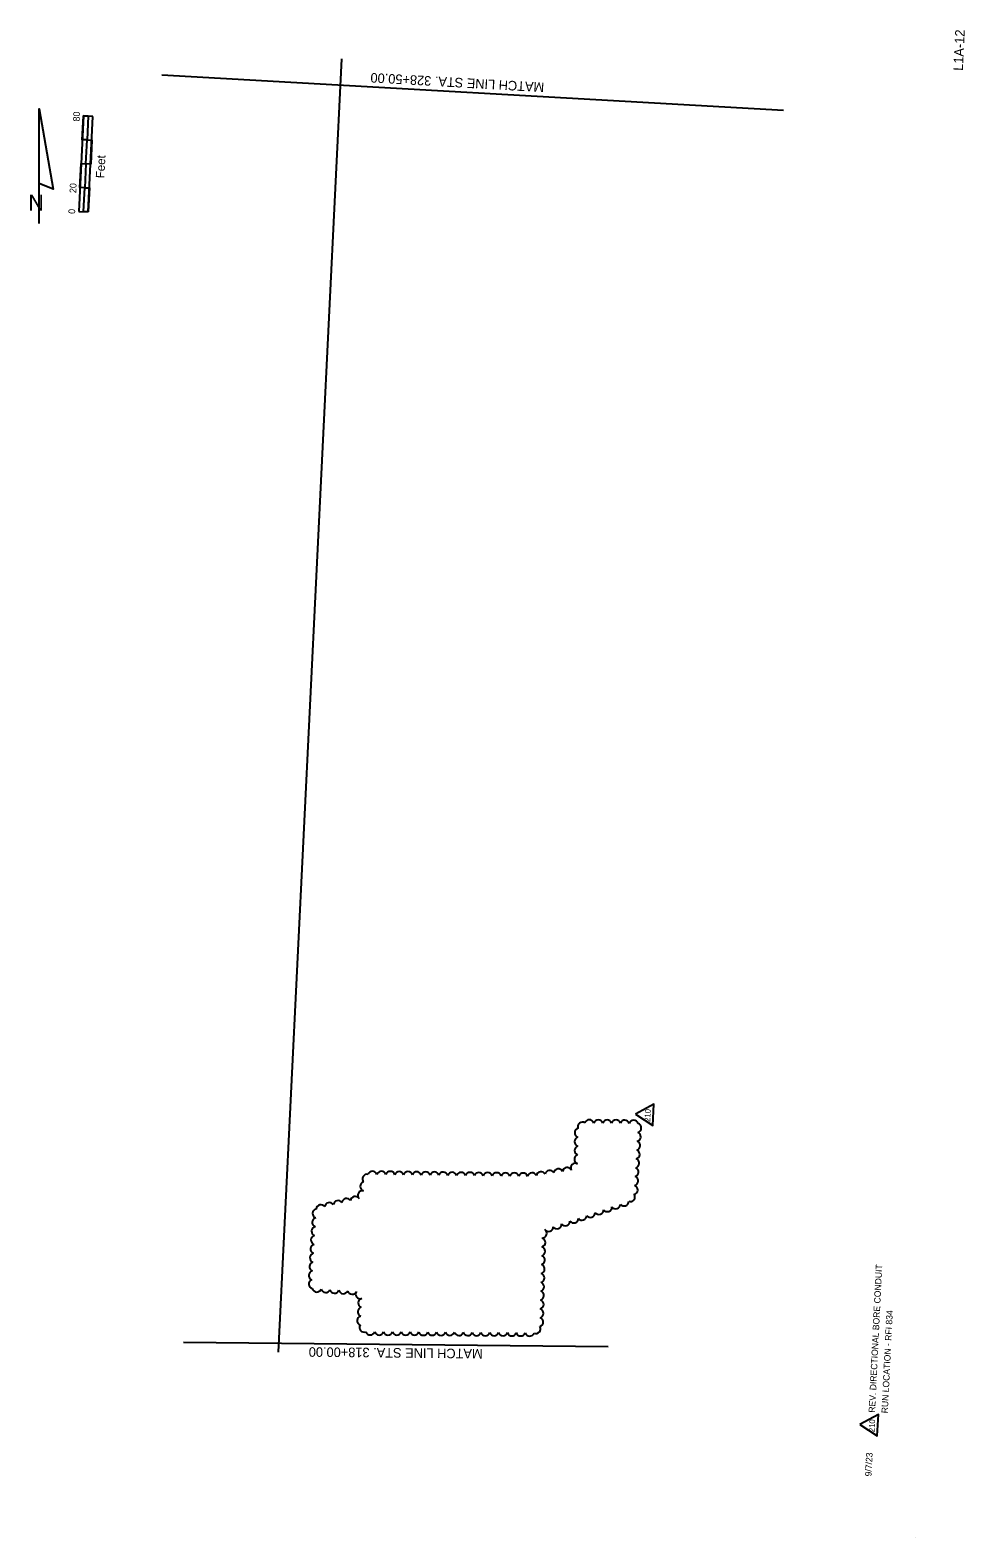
# Model space of a CAD drawing. Extents: x 929471 to 930252, y 607965 to 609226.
import ezdxf

# ---------------------------------------------------------------- set-up
doc = ezdxf.new("R2010")
doc.units = 0
for name, color, linetype in [('ActivePointCell_dp', 7, 'Continuous'), ('AdhocPoint_dp', 7, 'Continuous'), ('Cloud_dp', 7, 'Continuous'), ('NonPlottingEle_dp', 7, 'Continuous'), ('TextMinor', 7, 'Continuous'), ('TextMisc', 7, 'Continuous'), ('TextShtNo', 7, 'Continuous')]:
    doc.layers.add(name, color=color, linetype=linetype)

msp = doc.modelspace()

# ---------------------------------------------------------------- linework, layer by layer
at = {"layer": 'ActivePointCell_dp'}
msp.add_line((929678.7, 608120.4), (929731.6, 609202.3), dxfattribs=at)
at = {"layer": 'AdhocPoint_dp'}
msp.add_line((930211.2, 607965), (930211.2, 607965), dxfattribs=at)
at = {"layer": 'Cloud_dp'}
for points in [[(929977.1, 608319.4), (929991.7, 608310), (929992.6, 608327.7)], [(930164.7, 608059.8), (930179.3, 608050.4), (930180.2, 608068.1)]]:
    msp.add_lwpolyline(points, close=True, dxfattribs=at)
for centre, start, end in [((929932.7, 608308.9), 55.7899, 200.7899), ((929938.6, 608310.9), 16.7545, 161.7545), ((929946, 608310.8), 16.7545, 161.7545), ((929953.4, 608310.7), 16.7545, 161.7545), ((929960.8, 608310.7), 16.7545, 161.7545), ((929968.2, 608310.6), 16.7545, 161.7545), ((929975.6, 608310.5), 16.7545, 161.7545), ((929930.1, 608296.4), 106.7545, 251.7545), ((929930.2, 608303.9), 106.7545, 251.7545), ((929977.7, 608300.5), 284.0469, 69.0469), ((929978.1, 608307.9), 285.8603, 70.8603), ((929930, 608289), 106.7545, 251.7545), ((929976.8, 608285.8), 284.0469, 69.0469), ((929977.3, 608293.2), 284.0469, 69.0469), ((929920, 608271), 26.6528, 171.6528), ((929926.9, 608274.5), 62.613, 207.613), ((929929.9, 608281.6), 106.7545, 251.7545), ((929975.9, 608271), 284.0469, 69.0469), ((929976.4, 608278.4), 284.0469, 69.0469), ((929750.9, 608259), 106.7998, 251.7998), ((929752.7, 608265.3), 76.2735, 221.2735), ((929757.3, 608267.9), 16.7998, 161.7998), ((929764.7, 608267.8), 16.7998, 161.7998), ((929772.1, 608267.7), 16.7998, 161.7998), ((929779.5, 608267.6), 16.7998, 161.7998), ((929786.9, 608267.5), 16.7998, 161.7998), ((929794.3, 608267.4), 16.7998, 161.7998), ((929801.7, 608267.3), 16.7998, 161.7998), ((929809.1, 608267.2), 16.7998, 161.7998), ((929816.5, 608267.1), 16.7998, 161.7998), ((929823.9, 608267), 16.7998, 161.7998), ((929831.3, 608266.9), 16.7998, 161.7998), ((929838.7, 608266.9), 16.7998, 161.7998), ((929846.1, 608266.8), 16.7998, 161.7998), ((929853.5, 608266.7), 16.7998, 161.7998), ((929861, 608266.6), 16.7998, 161.7998), ((929868.4, 608266.5), 16.7998, 161.7998), ((929875.8, 608266.4), 16.7998, 161.7998), ((929883.2, 608266.3), 16.7998, 161.7998), ((929890.7, 608266.6), 21.8947, 166.8947), ((929898.1, 608267.4), 26.6528, 171.6528), ((929905.4, 608268.6), 26.6528, 171.6528), ((929912.7, 608269.8), 26.6528, 171.6528), ((929975.5, 608263.6), 284.0469, 69.0469), ((929735.6, 608245.1), 31.2001, 176.2001), ((929742.8, 608246.8), 31.2001, 176.2001), ((929748.9, 608251.5), 78.7411, 223.7411), ((929972.8, 608250.2), 249.8694, 34.8694), ((929975.1, 608256.2), 284.0469, 69.0469), ((929711.1, 608236.3), 103.9563, 248.9563), ((929714.1, 608239.8), 31.5788, 176.5788), ((929721.2, 608241.6), 31.2001, 176.2001), ((929728.4, 608243.3), 31.2001, 176.2001), ((929939.5, 608237), 216.1823, 1.1823), ((929946.6, 608239.4), 216.1823, 1.1823), ((929953.6, 608241.8), 216.1823, 1.1823), ((929960.6, 608244.1), 216.1823, 1.1823), ((929967.6, 608246.5), 216.1823, 1.1823), ((929710.2, 608221.5), 103.9563, 248.9563), ((929710.7, 608228.9), 103.9563, 248.9563), ((929904.5, 608225.2), 216.1823, 1.1823), ((929911.5, 608227.5), 216.1823, 1.1823), ((929918.5, 608229.9), 216.1823, 1.1823), ((929925.5, 608232.3), 216.1823, 1.1823), ((929932.5, 608234.6), 216.1823, 1.1823), ((929709.7, 608214.1), 103.9563, 248.9563), ((929897.9, 608212.1), 286.0161, 71.0161), ((929899.1, 608219.7), 270.1726, 55.1726), ((929708.8, 608199.3), 103.9563, 248.9563), ((929709.3, 608206.7), 103.9563, 248.9563), ((929897.5, 608197.3), 286.0161, 71.0161), ((929897.7, 608204.7), 286.0161, 71.0161), ((929707.9, 608184.5), 103.9563, 248.9563), ((929708.4, 608191.9), 103.9563, 248.9563), ((929897.1, 608182.5), 286.0161, 71.0161), ((929897.3, 608189.9), 286.0161, 71.0161), ((929707.9, 608177.3), 110.7092, 255.7092), ((929710.7, 608174.5), 193.9563, 338.9563), ((929718.1, 608174), 193.9563, 338.9563), ((929896.9, 608175.1), 286.0161, 71.0161), ((929725.5, 608173.5), 193.9563, 338.9563), ((929732.9, 608173.1), 193.9563, 338.9563), ((929740.3, 608172.6), 193.9563, 338.9563), ((929747, 608168.9), 143.9324, 288.9324), ((929749.2, 608161.5), 103.9563, 248.9563), ((929896.5, 608160.3), 286.0161, 71.0161), ((929896.7, 608167.7), 286.0161, 71.0161), ((929748.3, 608146.7), 103.9563, 248.9563), ((929748.8, 608154.1), 103.9563, 248.9563), ((929896.2, 608145.5), 286.0161, 71.0161), ((929896.3, 608152.9), 286.0161, 71.0161), ((929750.2, 608141), 147.5987, 292.5987), ((929755.4, 608138.6), 197.1364, 342.1364), ((929762.8, 608138.5), 197.1364, 342.1364), ((929770.2, 608138.5), 197.1364, 342.1364), ((929777.6, 608138.4), 197.1364, 342.1364), ((929785, 608138.4), 197.1364, 342.1364), ((929792.4, 608138.4), 197.1364, 342.1364), ((929799.8, 608138.3), 197.1364, 342.1364), ((929807.2, 608138.3), 197.1364, 342.1364), ((929814.6, 608138.2), 197.1364, 342.1364), ((929822, 608138.2), 197.1364, 342.1364), ((929829.4, 608138.1), 197.1364, 342.1364), ((929836.8, 608138.1), 197.1364, 342.1364), ((929844.2, 608138), 197.1364, 342.1364), ((929851.6, 608138), 197.1364, 342.1364), ((929859, 608137.9), 197.1364, 342.1364), ((929866.4, 608137.9), 197.1364, 342.1364), ((929873.8, 608137.8), 197.1364, 342.1364), ((929881.2, 608137.8), 197.1364, 342.1364), ((929888.7, 608137.6), 194.7007, 339.7007), ((929893.9, 608139.8), 246.0933, 31.0933)]:
    msp.add_arc(centre, 3.88, start, end, dxfattribs=at)
at = {"layer": 'NonPlottingEle_dp'}
for p, q in [((930100.8, 609159.2), (929581.1, 609188.6)), ((929954.2, 608124.8), (929599.2, 608128.5))]:
    msp.add_line(p, q, dxfattribs=at)
at = {"layer": 'TextMisc'}
for p, q in [((929515.6, 609154.6), (929511.7, 609074.7)), ((929523.6, 609154.2), (929515.6, 609154.6)), ((929519.7, 609074.3), (929523.6, 609154.2)), ((929511.7, 609074.7), (929519.7, 609074.3))]:
    msp.add_line(p, q, dxfattribs=at)
for points in [[(929518.6, 609134.5), (929514.6, 609134.6), (929515.6, 609154.6), (929519.6, 609154.4)], [(929521.7, 609114.3), (929517.7, 609114.5), (929518.6, 609134.5), (929522.6, 609134.3)], [(929516.7, 609094.5), (929512.7, 609094.7), (929513.7, 609114.7), (929517.7, 609114.5)], [(929519.7, 609074.3), (929515.7, 609074.5), (929516.7, 609094.5), (929520.7, 609094.3)]]:
    msp.add_lwpolyline(points, close=True, dxfattribs=at)
at = {"layer": 'TextShtNo'}
msp.add_line((929478.7, 609064.5), (929478.7, 609160.5), dxfattribs=at)
msp.add_lwpolyline([(929478.7, 609098.1), (929478.7, 609160.5), (929490.2, 609093.3)], close=True, dxfattribs=at)

# ---------------------------------------------------------------- texts
at = {"layer": 'Cloud_dp'}
for p in [(929989.4, 608312.9), (930177, 608053.3)]:
    msp.add_text('210', height=4.8, rotation=87.2007, dxfattribs=at).set_placement(p)
at = {"layer": 'NonPlottingEle_dp'}
for s, rotation, p in [('MATCH LINE STA. 328+50.00', 176.7666, (929901, 609182.4)), ('MATCH LINE STA. 318+00.00', 179.4, (929849.4, 608123))]:
    msp.add_text(s, height=8, rotation=rotation, dxfattribs=at).set_placement(p)
at = {"layer": 'TextMinor'}
for s, height, p in [('REV. DIRECTIONAL BORE CONDUIT ', 5.376, (930177.4, 608069.6)), ('RUN LOCATION - RFI 834', 5.376, (930188.1, 608069.1)), ('9/7/23', 5.38, (930174.4, 608016.3))]:
    msp.add_text(s, height=height, rotation=87.2007, dxfattribs=at).set_placement(p)
at = {"layer": 'TextMisc'}
for s, height, p in [('80', 5.6, (929512.4, 609149.8)), ('Feet', 7.2, (929533.1, 609102.3)), ('20', 5.6, (929509.5, 609089.9)), ('0', 5.6, (929508.6, 609072.5))]:
    msp.add_text(s, height=height, rotation=87.2418, dxfattribs=at).set_placement(p)
at = {"layer": 'TextShtNo'}
msp.add_text('L1A-12', height=8, rotation=87.2007, dxfattribs=at).set_placement((930250.8, 609192.2))
msp.add_text('N', height=13.4, dxfattribs=at).set_placement((929469.6, 609075.3))

doc.saveas('drawing.dxf')
